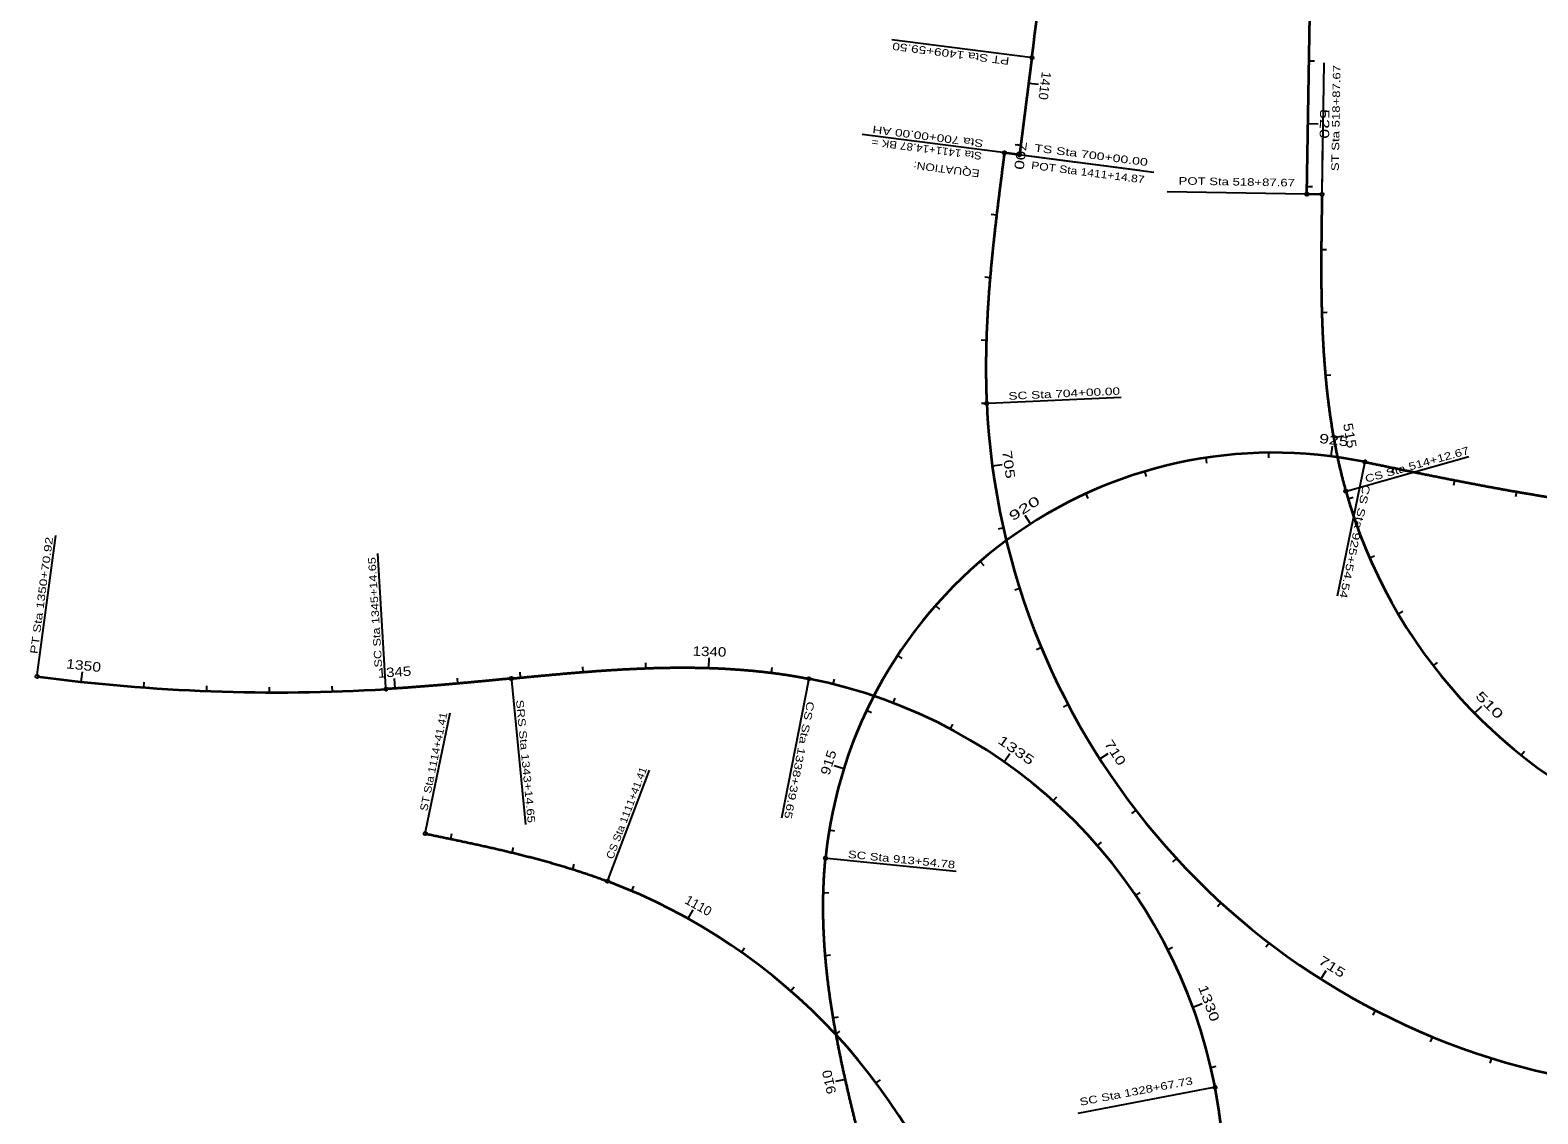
# Model space of a CAD drawing. Extents: x 771045 to 775849, y 632284 to 641017.
# Drawn here: x 771045 to 773443, y 635842 to 637565 of the extents above; entities that cross this region are included whole.
import ezdxf
from ezdxf.enums import TextEntityAlignment as Align

# ---------------------------------------------------------------- set-up
doc = ezdxf.new("R2010")
doc.units = 0
doc.header["$LTSCALE"] = 4.8
for name, color, linetype, lineweight in [('1', 7, 'Continuous', 35), ('30', 7, 'Continuous', 25), ('33', 7, 'Continuous', 25)]:
    doc.layers.add(name, color=color, linetype=linetype, lineweight=lineweight)

msp = doc.modelspace()

# ---------------------------------------------------------------- linework, layer by layer
at = {"layer": '1'}
for points in [[(773099.539, 637303.776), (773075.542, 637304.177), (773086.114, 637936.209)], [(772638.146, 637521.083), (772618.228, 637366.997), (772594.426, 637370.074)]]:
    msp.add_lwpolyline(points, dxfattribs=at)
for centre, radius, start, end in [((766955.847, 638255.612), 5729.578, 352.63444, 358.83333), ((773711.036, 637024.275), 1145.916, 182.63444, 260.02666), ((773022.67, 636177.128), 716.197, 78.29806, 174.27889), ((773925.423, 637053.092), 818.511, 195.66665, 248.87721), ((771436.91, 639376.826), 2864.789, 262.36, 273.48528), ((772125.435, 635730.612), 818.511, 10.82556, 78.86028), ((771626.667, 635318.157), 954.93, 16.5, 69.36)]:
    msp.add_arc(centre, radius, start, end, dxfattribs=at)
for points in [[(772594.426, 637370.074), (772593.733, 637364.713), (772593.041, 637359.352), (772592.349, 637353.991), (772591.658, 637348.63), (772590.969, 637343.269), (772590.281, 637337.908), (772589.595, 637332.546), (772588.912, 637327.184), (772588.231, 637321.821), (772587.554, 637316.459), (772586.879, 637311.095), (772586.209, 637305.732), (772585.543, 637300.368), (772584.881, 637295.003), (772584.224, 637289.638), (772583.572, 637284.272), (772582.926, 637278.905), (772582.285, 637273.538), (772581.651, 637268.17), (772581.023, 637262.801), (772580.402, 637257.431), (772579.788, 637252.061), (772579.181, 637246.689), (772578.583, 637241.317), (772577.993, 637235.944), (772577.411, 637230.57), (772576.838, 637225.195), (772576.275, 637219.819), (772575.721, 637214.442), (772575.177, 637209.064), (772574.643, 637203.686), (772574.12, 637198.305), (772573.608, 637192.924), (772573.107, 637187.542), (772572.618, 637182.159), (772572.141, 637176.775), (772571.676, 637171.389), (772571.224, 637166.003), (772570.785, 637160.615), (772570.359, 637155.227), (772569.947, 637149.837), (772569.549, 637144.446), (772569.166, 637139.054), (772568.797, 637133.662), (772568.444, 637128.268), (772568.106, 637122.873), (772567.784, 637117.477), (772567.478, 637112.08), (772567.188, 637106.683), (772566.916, 637101.284), (772566.66, 637095.885), (772566.423, 637090.485), (772566.203, 637085.084), (772566.001, 637079.682), (772565.818, 637074.28), (772565.654, 637068.877), (772565.509, 637063.473), (772565.383, 637058.069), (772565.278, 637052.665), (772565.193, 637047.26), (772565.129, 637041.855), (772565.086, 637036.45), (772565.064, 637031.045), (772565.064, 637025.639), (772565.086, 637020.234), (772565.13, 637014.829), (772565.197, 637009.424), (772565.287, 637004.019), (772565.4, 636998.615), (772565.538, 636993.211), (772565.699, 636987.808), (772565.885, 636982.406), (772566.096, 636977.005), (772566.331, 636971.605)], [(773099.539, 637303.776), (773099.431, 637297.358), (773099.325, 637290.94), (773099.22, 637284.522), (773099.116, 637278.103), (773099.016, 637271.685), (773098.919, 637265.267), (773098.826, 637258.849), (773098.738, 637252.431), (773098.655, 637246.012), (773098.578, 637239.594), (773098.508, 637233.175), (773098.446, 637226.757), (773098.392, 637220.338), (773098.347, 637213.919), (773098.311, 637207.5), (773098.285, 637201.081), (773098.27, 637194.662), (773098.267, 637188.244), (773098.276, 637181.825), (773098.298, 637175.406), (773098.334, 637168.987), (773098.384, 637162.568), (773098.449, 637156.15), (773098.529, 637149.731), (773098.626, 637143.313), (773098.74, 637136.895), (773098.871, 637130.478), (773099.021, 637124.06), (773099.19, 637117.644), (773099.379, 637111.228), (773099.588, 637104.812), (773099.818, 637098.397), (773100.07, 637091.983), (773100.344, 637085.57), (773100.641, 637079.158), (773100.962, 637072.747), (773101.308, 637066.338), (773101.679, 637059.93), (773102.075, 637053.523), (773102.498, 637047.118), (773102.949, 637040.715), (773103.427, 637034.314), (773103.933, 637027.915), (773104.469, 637021.518), (773105.034, 637015.124), (773105.63, 637008.733), (773106.257, 637002.345), (773106.916, 636995.96), (773107.608, 636989.578), (773108.332, 636983.201), (773109.09, 636976.826), (773109.883, 636970.457), (773110.711, 636964.091), (773111.574, 636957.731), (773112.474, 636951.375), (773113.411, 636945.025), (773114.386, 636938.681), (773115.399, 636932.342), (773116.451, 636926.01), (773117.542, 636919.685), (773118.674, 636913.366), (773119.846, 636907.055), (773121.06, 636900.752), (773122.316, 636894.458), (773123.615, 636888.171), (773124.957, 636881.894), (773126.343, 636875.627), (773127.773, 636869.369), (773129.248, 636863.122), (773130.769, 636856.886), (773132.336, 636850.661), (773133.95, 636844.449), (773135.611, 636838.248), (773137.321, 636832.061)], [(773167.929, 636878.44), (773174.545, 636877.07), (773181.162, 636875.7), (773187.778, 636874.33), (773194.395, 636872.962), (773201.012, 636871.595), (773207.629, 636870.229), (773214.247, 636868.865), (773220.865, 636867.504), (773227.484, 636866.145), (773234.103, 636864.789), (773240.723, 636863.436), (773247.344, 636862.086), (773253.965, 636860.74), (773260.587, 636859.399), (773267.21, 636858.062), (773273.835, 636856.729), (773280.46, 636855.402), (773287.086, 636854.08), (773293.713, 636852.764), (773300.342, 636851.454), (773306.971, 636850.15), (773313.602, 636848.853), (773320.235, 636847.562), (773326.869, 636846.279), (773333.504, 636845.004), (773340.141, 636843.737), (773346.779, 636842.478), (773353.419, 636841.227), (773360.061, 636839.985), (773366.704, 636838.753), (773373.35, 636837.53), (773379.996, 636836.317), (773386.645, 636835.114), (773393.296, 636833.922), (773399.949, 636832.74), (773406.603, 636831.569), (773413.26, 636830.41), (773419.918, 636829.263), (773426.579, 636828.128), (773433.242, 636827.005), (773439.907, 636825.895), (773446.574, 636824.798), (773453.243, 636823.715), (773459.915, 636822.645), (773466.589, 636821.589), (773473.265, 636820.548), (773479.943, 636819.521), (773486.624, 636818.509), (773493.306, 636817.513), (773499.992, 636816.532), (773506.679, 636815.568), (773513.369, 636814.619), (773520.061, 636813.687), (773526.756, 636812.772), (773533.453, 636811.875), (773540.152, 636810.995), (773546.853, 636810.133), (773553.557, 636809.289), (773560.263, 636808.464), (773566.972, 636807.658), (773573.683, 636806.871), (773580.396, 636806.103), (773587.111, 636805.356), (773593.828, 636804.628), (773600.548, 636803.922), (773607.27, 636803.236), (773613.994, 636802.571), (773620.72, 636801.928), (773627.448, 636801.307), (773634.178, 636800.708), (773640.91, 636800.131), (773647.645, 636799.578), (773654.38, 636799.047), (773661.118, 636798.54)], [(771810.349, 636534.135), (771816.738, 636534.748), (771823.128, 636535.361), (771829.518, 636535.972), (771835.908, 636536.582), (771842.298, 636537.189), (771848.688, 636537.792), (771855.079, 636538.391), (771861.47, 636538.986), (771867.862, 636539.575), (771874.255, 636540.158), (771880.648, 636540.734), (771887.041, 636541.303), (771893.436, 636541.863), (771899.831, 636542.415), (771906.227, 636542.957), (771912.624, 636543.49), (771919.021, 636544.011), (771925.42, 636544.521), (771931.82, 636545.018), (771938.22, 636545.503), (771944.622, 636545.974), (771951.024, 636546.431), (771957.428, 636546.873), (771963.833, 636547.299), (771970.239, 636547.709), (771976.646, 636548.103), (771983.053, 636548.478), (771989.462, 636548.835), (771995.872, 636549.173), (772002.283, 636549.491), (772008.695, 636549.789), (772015.108, 636550.066), (772021.522, 636550.321), (772027.937, 636550.554), (772034.352, 636550.764), (772040.769, 636550.95), (772047.186, 636551.111), (772053.603, 636551.247), (772060.021, 636551.358), (772066.439, 636551.441), (772072.858, 636551.498), (772079.277, 636551.527), (772085.696, 636551.527), (772092.115, 636551.498), (772098.533, 636551.439), (772104.952, 636551.349), (772111.369, 636551.228), (772117.786, 636551.075), (772124.203, 636550.89), (772130.618, 636550.671), (772137.032, 636550.418), (772143.444, 636550.13), (772149.855, 636549.808), (772156.264, 636549.449), (772162.671, 636549.053), (772169.075, 636548.62), (772175.477, 636548.15), (772181.875, 636547.64), (772188.271, 636547.091), (772194.662, 636546.502), (772201.05, 636545.873), (772207.434, 636545.202), (772213.813, 636544.49), (772220.188, 636543.735), (772226.557, 636542.936), (772232.92, 636542.094), (772239.278, 636541.207), (772245.628, 636540.275), (772251.972, 636539.297), (772258.309, 636538.274), (772264.638, 636537.203), (772270.959, 636536.084), (772277.271, 636534.917), (772283.574, 636533.702)], [(771810.349, 636534.135), (771807.658, 636533.876), (771804.968, 636533.618), (771802.278, 636533.36), (771799.587, 636533.102), (771796.897, 636532.844), (771794.207, 636532.586), (771791.516, 636532.328), (771788.826, 636532.071), (771786.135, 636531.814), (771783.445, 636531.557), (771780.754, 636531.3), (771778.064, 636531.044), (771775.373, 636530.789), (771772.683, 636530.534), (771769.992, 636530.279), (771767.301, 636530.024), (771764.611, 636529.771), (771761.92, 636529.518), (771759.229, 636529.265), (771756.538, 636529.013), (771753.847, 636528.762), (771751.156, 636528.512), (771748.465, 636528.262), (771745.773, 636528.013), (771743.082, 636527.765), (771740.391, 636527.518), (771737.699, 636527.272), (771735.008, 636527.026), (771732.316, 636526.782), (771729.624, 636526.539), (771726.933, 636526.296), (771724.241, 636526.055), (771721.549, 636525.815), (771718.856, 636525.576), (771716.164, 636525.338), (771713.472, 636525.101), (771710.78, 636524.865), (771708.087, 636524.631), (771705.394, 636524.398), (771702.702, 636524.167), (771700.009, 636523.936), (771697.316, 636523.708), (771694.623, 636523.48), (771691.929, 636523.254), (771689.236, 636523.03), (771686.543, 636522.807), (771683.849, 636522.586), (771681.155, 636522.366), (771678.461, 636522.148), (771675.767, 636521.932), (771673.073, 636521.717), (771670.379, 636521.505), (771667.684, 636521.294), (771664.99, 636521.084), (771662.295, 636520.877), (771659.6, 636520.671), (771656.905, 636520.468), (771654.21, 636520.266), (771651.515, 636520.067), (771648.819, 636519.869), (771646.123, 636519.674), (771643.428, 636519.48), (771640.732, 636519.289), (771638.036, 636519.1), (771635.339, 636518.913), (771632.643, 636518.728), (771629.947, 636518.546), (771627.25, 636518.366), (771624.553, 636518.188), (771621.856, 636518.012), (771619.159, 636517.84), (771616.462, 636517.669), (771613.764, 636517.501), (771611.066, 636517.335)], [(771673.333, 636287.53), (771677.304, 636286.712), (771681.274, 636285.894), (771685.245, 636285.075), (771689.215, 636284.256), (771693.185, 636283.436), (771697.155, 636282.614), (771701.125, 636281.792), (771705.094, 636280.967), (771709.063, 636280.141), (771713.032, 636279.313), (771717, 636278.482), (771720.967, 636277.649), (771724.934, 636276.814), (771728.901, 636275.975), (771732.866, 636275.133), (771736.831, 636274.288), (771740.796, 636273.439), (771744.759, 636272.586), (771748.721, 636271.729), (771752.683, 636270.868), (771756.643, 636270.002), (771760.603, 636269.131), (771764.561, 636268.256), (771768.519, 636267.375), (771772.475, 636266.489), (771776.429, 636265.597), (771780.383, 636264.699), (771784.335, 636263.795), (771788.285, 636262.885), (771792.234, 636261.968), (771796.182, 636261.045), (771800.127, 636260.114), (771804.072, 636259.176), (771808.014, 636258.231), (771811.954, 636257.278), (771815.893, 636256.317), (771819.829, 636255.348), (771823.764, 636254.37), (771827.696, 636253.384), (771831.626, 636252.39), (771835.554, 636251.386), (771839.479, 636250.373), (771843.402, 636249.35), (771847.323, 636248.318), (771851.241, 636247.276), (771855.156, 636246.224), (771859.068, 636245.161), (771862.978, 636244.088), (771866.884, 636243.004), (771870.788, 636241.91), (771874.688, 636240.804), (771878.585, 636239.686), (771882.479, 636238.557), (771886.369, 636237.416), (771890.255, 636236.263), (771894.138, 636235.098), (771898.018, 636233.921), (771901.893, 636232.73), (771905.764, 636231.527), (771909.632, 636230.311), (771913.495, 636229.081), (771917.354, 636227.838), (771921.208, 636226.581), (771925.058, 636225.311), (771928.903, 636224.026), (771932.743, 636222.727), (771936.578, 636221.413), (771940.408, 636220.084), (771944.233, 636218.741), (771948.053, 636217.382), (771951.867, 636216.009), (771955.676, 636214.619), (771959.479, 636213.214), (771963.275, 636211.793)], [(772375.975, 635755.616), (772374.309, 635762.164), (772372.643, 635768.713), (772370.979, 635775.261), (772369.318, 635781.811), (772367.66, 635788.361), (772366.006, 635794.912), (772364.357, 635801.465), (772362.714, 635808.018), (772361.078, 635814.574), (772359.449, 635821.132), (772357.829, 635827.691), (772356.218, 635834.253), (772354.616, 635840.817), (772353.026, 635847.384), (772351.448, 635853.954), (772349.882, 635860.527), (772348.329, 635867.103), (772346.791, 635873.682), (772345.267, 635880.265), (772343.76, 635886.851), (772342.27, 635893.442), (772340.797, 635900.036), (772339.343, 635906.634), (772337.908, 635913.237), (772336.493, 635919.844), (772335.099, 635926.455), (772333.727, 635933.071), (772332.378, 635939.692), (772331.053, 635946.318), (772329.752, 635952.948), (772328.477, 635959.583), (772327.227, 635966.223), (772326.005, 635972.869), (772324.811, 635979.519), (772323.646, 635986.175), (772322.51, 635992.835), (772321.405, 635999.501), (772320.332, 636006.172), (772319.29, 636012.848), (772318.282, 636019.529), (772317.308, 636026.215), (772316.369, 636032.907), (772315.466, 636039.603), (772314.6, 636046.304), (772313.771, 636053.009), (772312.98, 636059.72), (772312.229, 636066.435), (772311.519, 636073.154), (772310.849, 636079.877), (772310.222, 636086.605), (772309.637, 636093.336), (772309.096, 636100.071), (772308.6, 636106.81), (772308.149, 636113.552), (772307.745, 636120.296), (772307.388, 636127.044), (772307.079, 636133.793), (772306.819, 636140.545), (772306.609, 636147.298), (772306.45, 636154.053), (772306.343, 636160.809), (772306.288, 636167.566), (772306.287, 636174.322), (772306.34, 636181.079), (772306.448, 636187.835), (772306.612, 636194.59), (772306.832, 636201.343), (772307.111, 636208.094), (772307.448, 636214.842), (772307.844, 636221.587), (772308.301, 636228.328), (772308.818, 636235.065), (772309.398, 636241.797), (772310.04, 636248.523)], [(772927.218, 635411.124), (772927.867, 635417.51), (772928.514, 635423.897), (772929.161, 635430.283), (772929.805, 635436.669), (772930.447, 635443.056), (772931.085, 635449.443), (772931.72, 635455.831), (772932.349, 635462.219), (772932.973, 635468.607), (772933.591, 635474.996), (772934.203, 635481.386), (772934.807, 635487.777), (772935.402, 635494.168), (772935.989, 635500.56), (772936.566, 635506.953), (772937.134, 635513.346), (772937.69, 635519.741), (772938.235, 635526.137), (772938.768, 635532.534), (772939.287, 635538.932), (772939.794, 635545.331), (772940.286, 635551.73), (772940.763, 635558.132), (772941.224, 635564.534), (772941.669, 635570.938), (772942.098, 635577.342), (772942.508, 635583.748), (772942.9, 635590.155), (772943.274, 635596.563), (772943.627, 635602.972), (772943.96, 635609.382), (772944.272, 635615.794), (772944.563, 635622.206), (772944.831, 635628.619), (772945.075, 635635.034), (772945.296, 635641.449), (772945.493, 635647.865), (772945.664, 635654.281), (772945.81, 635660.698), (772945.929, 635667.116), (772946.021, 635673.534), (772946.084, 635679.953), (772946.12, 635686.372), (772946.126, 635692.791), (772946.102, 635699.21), (772946.048, 635705.628), (772945.962, 635712.047), (772945.844, 635718.465), (772945.694, 635724.882), (772945.51, 635731.298), (772945.292, 635737.713), (772945.04, 635744.127), (772944.752, 635750.54), (772944.429, 635756.95), (772944.068, 635763.359), (772943.671, 635769.766), (772943.235, 635776.17), (772942.761, 635782.571), (772942.247, 635788.97), (772941.693, 635795.365), (772941.099, 635801.756), (772940.463, 635808.143), (772939.785, 635814.526), (772939.065, 635820.905), (772938.302, 635827.278), (772937.494, 635833.646), (772936.642, 635840.008), (772935.745, 635846.364), (772934.802, 635852.713), (772933.813, 635859.055), (772932.777, 635865.39), (772931.693, 635871.717), (772930.561, 635878.035), (772929.38, 635884.344)]]:
    msp.add_spline(points, degree=3, dxfattribs=at)
at = {"layer": '30'}
for p, q in [((773079.093, 637516.478), (773087.592, 637516.336)), ((772632.954, 637480.916), (772648.822, 637478.865)), ((773077.421, 637416.492), (773093.418, 637416.224)), ((772594.426, 637370.074), (772610.294, 637368.023)), ((772620.134, 637381.741), (772611.704, 637382.831)), ((773075.748, 637316.506), (773084.247, 637316.363)), ((772581.967, 637270.854), (772573.526, 637271.851)), ((773098.361, 637216.114), (773106.861, 637216.056)), ((772571.676, 637171.389), (772563.206, 637172.11)), ((773099.233, 637116.123), (773107.729, 637116.366)), ((772565.733, 637071.578), (772557.237, 637071.837)), ((773104.928, 637016.301), (773113.394, 637017.063)), ((772566.331, 636971.605), (772557.84, 636971.214)), ((773117.984, 636917.189), (773133.736, 636919.999)), ((772914.816, 636885.158), (772916.096, 636876.755)), ((773014.404, 636893.278), (773014.502, 636884.778)), ((773114.153, 636887.459), (773116.197, 636903.328)), ((772575.278, 636872.037), (772591.136, 636874.163)), ((772817.327, 636863.257), (772819.764, 636855.114)), ((773212.448, 636869.236), (773210.733, 636860.911)), ((773310.473, 636849.464), (773308.841, 636841.122)), ((772723.834, 636828.002), (772727.381, 636820.277)), ((773140.836, 636819.889), (773148.984, 636822.311)), ((773408.787, 636831.188), (773407.326, 636822.814)), ((772636.159, 636780.077), (772627.524, 636793.547)), ((772592.868, 636773.629), (772584.574, 636771.77)), ((772556.006, 636720.418), (772561.544, 636713.97)), ((773175.105, 636726.01), (773182.897, 636729.407)), ((772618.968, 636677.128), (772610.868, 636674.553)), ((772484.936, 636650.183), (772491.318, 636644.569)), ((773220.559, 636637.008), (773227.879, 636641.329)), ((772653.38, 636583.269), (772645.534, 636579.998)), ((771924.537, 636544.451), (771923.867, 636552.925)), ((772024.351, 636550.427), (772024.041, 636558.921)), ((772124.33, 636550.886), (772124.836, 636566.878)), ((772224.002, 636543.262), (772225.065, 636551.695)), ((772424.333, 636570.742), (772431.434, 636566.07)), ((773276.521, 636554.208), (773283.259, 636559.388)), ((771126.439, 636528.91), (771128.173, 636544.816)), ((771226.019, 636519.81), (771226.645, 636528.287)), ((771625.692, 636518.263), (771624.64, 636534.228)), ((771725.377, 636526.157), (771724.619, 636534.623)), ((771824.936, 636535.534), (771824.126, 636543.995)), ((772322.28, 636525.101), (772324.324, 636533.351)), ((771325.856, 636514.19), (771326.186, 636522.684)), ((771425.828, 636512.058), (771425.861, 636520.558)), ((771525.814, 636513.417), (771525.55, 636521.912)), ((772417.637, 636495.19), (772420.671, 636503.13)), ((772375.375, 636483.639), (772383.057, 636480.001)), ((772695.841, 636492.766), (772688.31, 636488.824)), ((773342.156, 636478.845), (773353.558, 636490.07)), ((772508.637, 636453.88), (772512.617, 636461.391)), ((772593.925, 636401.789), (772603.083, 636414.908)), ((772746.028, 636406.309), (772759.502, 636414.937)), ((773416.487, 636412.043), (773421.772, 636418.7)), ((772339.017, 636390.57), (772323.744, 636395.338)), ((772672.229, 636339.691), (772677.907, 636346.016)), ((772803.559, 636324.554), (772796.828, 636319.364)), ((771713.88, 636279.136), (771715.619, 636287.456)), ((772315.965, 636293.346), (772324.352, 636291.967)), ((771811.483, 636257.392), (771813.487, 636265.653)), ((772742.381, 636268.514), (772748.788, 636274.1)), ((771907.88, 636230.863), (771910.432, 636238.972)), ((772867.997, 636248.125), (772861.744, 636242.368)), ((772001.696, 636196.362), (772005.034, 636204.179)), ((772306.591, 636193.864), (772315.088, 636193.63)), ((772803.336, 636189.318), (772810.376, 636194.081)), ((772091.439, 636152.35), (772099.226, 636166.327)), ((772938.851, 636177.603), (772933.123, 636171.323)), ((772176.09, 636099.198), (772180.98, 636106.151)), ((772309.585, 636093.96), (772318.056, 636094.663)), ((772854.186, 636103.283), (772861.753, 636107.153)), ((773015.582, 636113.524), (773010.423, 636106.769)), ((773097.605, 636056.377), (773106.17, 636069.892)), ((772254.721, 636037.49), (772260.311, 636043.892)), ((772322.184, 635994.785), (772330.568, 635996.184)), ((772894.171, 636011.693), (772909.198, 636017.187)), ((773184.297, 636006.596), (773180.39, 635999.048)), ((772326.471, 635967.899), (772332.7, 635973.683)), ((773274.998, 635964.561), (773271.764, 635956.7)), ((773369.018, 635930.59), (773366.481, 635922.478)), ((772922.696, 635915.912), (772930.975, 635917.837)), ((772341.542, 635896.69), (772325.927, 635893.202)), ((772390.554, 635891.191), (772397.354, 635896.291))]:
    msp.add_line(p, q, dxfattribs=at)
at = {"layer": '33'}
for p, q in [((772635.469, 637521.429), (772415.566, 637549.855)), ((773099.584, 637306.475), (773103.039, 637513.061)), ((772591.749, 637370.42), (772367.981, 637399.346)), ((773099.584, 637306.475), (773101.074, 637395.557)), ((772597.104, 637369.728), (772809.744, 637342.241)), ((772620.906, 637366.651), (772709.265, 637355.229)), ((772620.906, 637366.651), (772831.906, 637339.376)), ((773072.842, 637304.222), (772853.031, 637307.899)), ((772569.029, 636971.729), (772780.38, 636981.453)), ((773139.92, 636832.791), (773332.945, 636886.926)), ((773167.381, 636875.796), (773123.703, 636664.918)), ((771056.4, 636540.144), (771086.067, 636761.312)), ((771610.902, 636520.03), (771597.94, 636732.864)), ((771810.607, 636531.447), (771832.66, 636301.795)), ((772283.052, 636531.053), (772239.893, 636311.876)), ((771673.878, 636290.175), (771712.943, 636479.815)), ((771964.227, 636214.32), (772029.897, 636388.661)), ((772312.726, 636248.254), (772517.724, 636227.716)), ((772926.728, 635883.837), (772711.03, 635842.591))]:
    msp.add_line(p, q, dxfattribs=at)
for centre in [(772638.146, 637521.083), (772594.426, 637370.074), (772594.426, 637370.074), (772618.228, 637366.997), (772618.228, 637366.997), (773075.542, 637304.177), (773099.539, 637303.776), (773099.539, 637303.776), (772566.331, 636971.605), (773167.929, 636878.44), (773137.321, 636832.061), (771056.041, 636537.468), (771810.349, 636534.135), (772283.574, 636533.702), (771611.066, 636517.335), (771673.333, 636287.53), (772310.04, 636248.523), (771963.275, 636211.793), (772929.38, 635884.344)]:
    msp.add_circle(centre, 2.7, dxfattribs=at)

# ---------------------------------------------------------------- texts
at = {"layer": '30'}
for s, rotation, p in [('1410', 262.634, (772651.375, 637477.557)), ('1110', 330.876, (772104.191, 636166.652))]:
    msp.add_text(s, height=15, rotation=rotation, dxfattribs=at).set_placement(p, align=Align.CENTER)
for s, rotation, width, p in [('520', 269.042, 1.4, (773096.116, 637416.053)), ('700', 262.634, 1.35, (772612.848, 637366.715)), ('515', 280.115, 1.2, (773136.628, 636919.156)), ('925', 352.661, 1.4, (773117.5, 636905.882)), ('705', 277.634, 1.35, (772593.946, 636873.525)), ('920', 32.661, 1.6, (772630.114, 636798.415)), ('1340', 358.19, 1.2, (772125.158, 636569.569)), ('1350', 353.778, 1.25, (771129.279, 636547.411)), ('1345', 3.768, 1.2, (771624.956, 636536.955)), ('510', 314.554, 1.55, (773360.662, 636486.703)), ('1335', 325.084, 1.45, (772608.921, 636414.126)), ('710', 302.634, 1.3, (772764.366, 636412.349)), ('915', 72.661, 1.2, (772321.864, 636398.378)), ('715', 327.634, 1.35, (773111.63, 636069.628)), ('1330', 290.084, 1.35, (772912.675, 636015.539)), ('910', 102.592, 1.15, (772322.926, 635894.248))]:
    msp.add_text(s, height=15, rotation=rotation, dxfattribs=dict(at, width=width)).set_placement(p, align=Align.CENTER)
at = {"layer": '33'}
for s, rotation, width, p in [('PT Sta 1409+59.50', 172.634, 1.35, (772602.922, 637521.603)), ('ST Sta 518+87.67', 89.042, 1.3, (773126.192, 637340.804)), ('Sta 700+00.00 AH', 172.634, 1.35, (772561.766, 637390.429)), ('Sta 1411+14.87 BK = ', 172.634, 1.15, (772559.202, 637370.594)), ('TS Sta 700+00.00', 352.635, 1.4, (772641.44, 637372.17)), ('EQUATION:', 172.634, 1.2, (772555.613, 637342.825)), ('POT Sta 1411+14.87', 352.634, 1.2, (772636.504, 637344.484)), ('POT Sta 518+87.67', 359.042, 1.3, (772871.463, 637319.479)), ('SC Sta 704+00.00', 2.634, 1.35, (772601.11, 636977.209)), ('CS Sta 514+12.67', 15.667, 1.3, (773169.94, 636845.364)), ('CS Sta 925+54.54', 258.298, 1.4, (773164.747, 636843.356)), ('PT Sta 1350+70.92', 82.36, 1.35, (771056.73, 636572.689)), ('SC Sta 1345+14.65', 93.485, 1.25, (771604.946, 636552.027)), ('ST Sta 1114+41.41', 78.36, 1.15, (771676.477, 636322.617)), ('SRS Sta 1343+14.65', 275.485, 1.3, (771817.676, 636499.677)), ('CS Sta 1338+39.65', 258.86, 1.35, (772280.736, 636498.588)), ('CS Sta 1111+41.41', 69.36, 1.1, (771971.87, 636245.956)), ('SC Sta 913+54.78', 354.279, 1.3, (772345.264, 636249.014)), ('SC Sta 1328+67.73', 10.826, 1.3, (772715.385, 635854.766))]:
    msp.add_text(s, height=12, rotation=rotation, dxfattribs=dict(at, width=width)).set_placement(p)

doc.saveas('drawing.dxf')
